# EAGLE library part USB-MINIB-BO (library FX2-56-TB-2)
USB MiniB-Buchse Oberflächenmontage
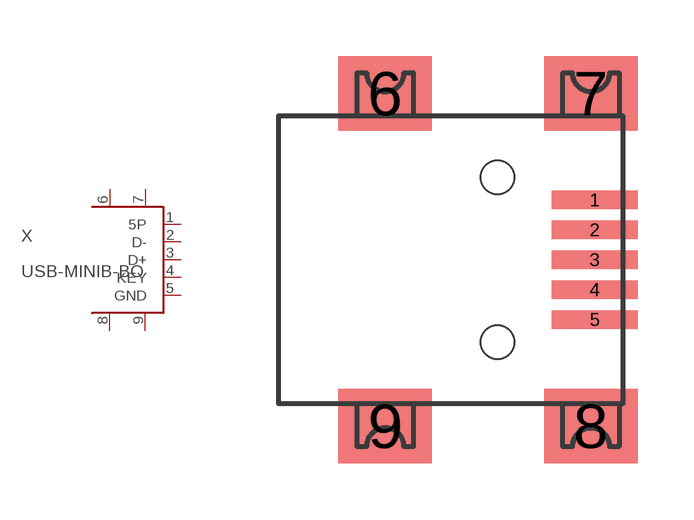
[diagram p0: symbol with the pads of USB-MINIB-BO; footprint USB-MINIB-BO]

Designator prefix X

## USB-MINIB-BO  [USB-MINIB-BO]
1  5P  sup
2  D-
3  D+
4  KEY
5  GND  pwr
6  GND  pwr
7  GND  pwr
8  GND  pwr
9  GND  pwr

## Footprint USB-MINIB-BO (pad centres in mm)
USB-MiniB-Buchse Oberflächenmontage (regulär)
smd 2.3 x 0.5: 1 7.85,1.6; 2 7.85,0.8; 3 7.85,0; 4 7.85,-0.8; 5 7.85,-1.6
smd 2.5 x 2: 6 2.25,4.45; 7 7.75,4.45; 8 7.75,-4.45; 9 2.25,-4.45
hole 0.9 at 5.25,2.2
hole 0.9 at 5.25,-2.2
